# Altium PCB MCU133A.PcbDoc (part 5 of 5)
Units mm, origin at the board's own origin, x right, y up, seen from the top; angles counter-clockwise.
Board outline 58.42 x 139.7 mm, 4 copper layers (Top Signal, GND, PWR, Bottom Signal), stack 1.565 mm thick; 278 components, 226 nets, 1057 pads, 868 vias.
Unrouted connection lines stored in the file: 237.
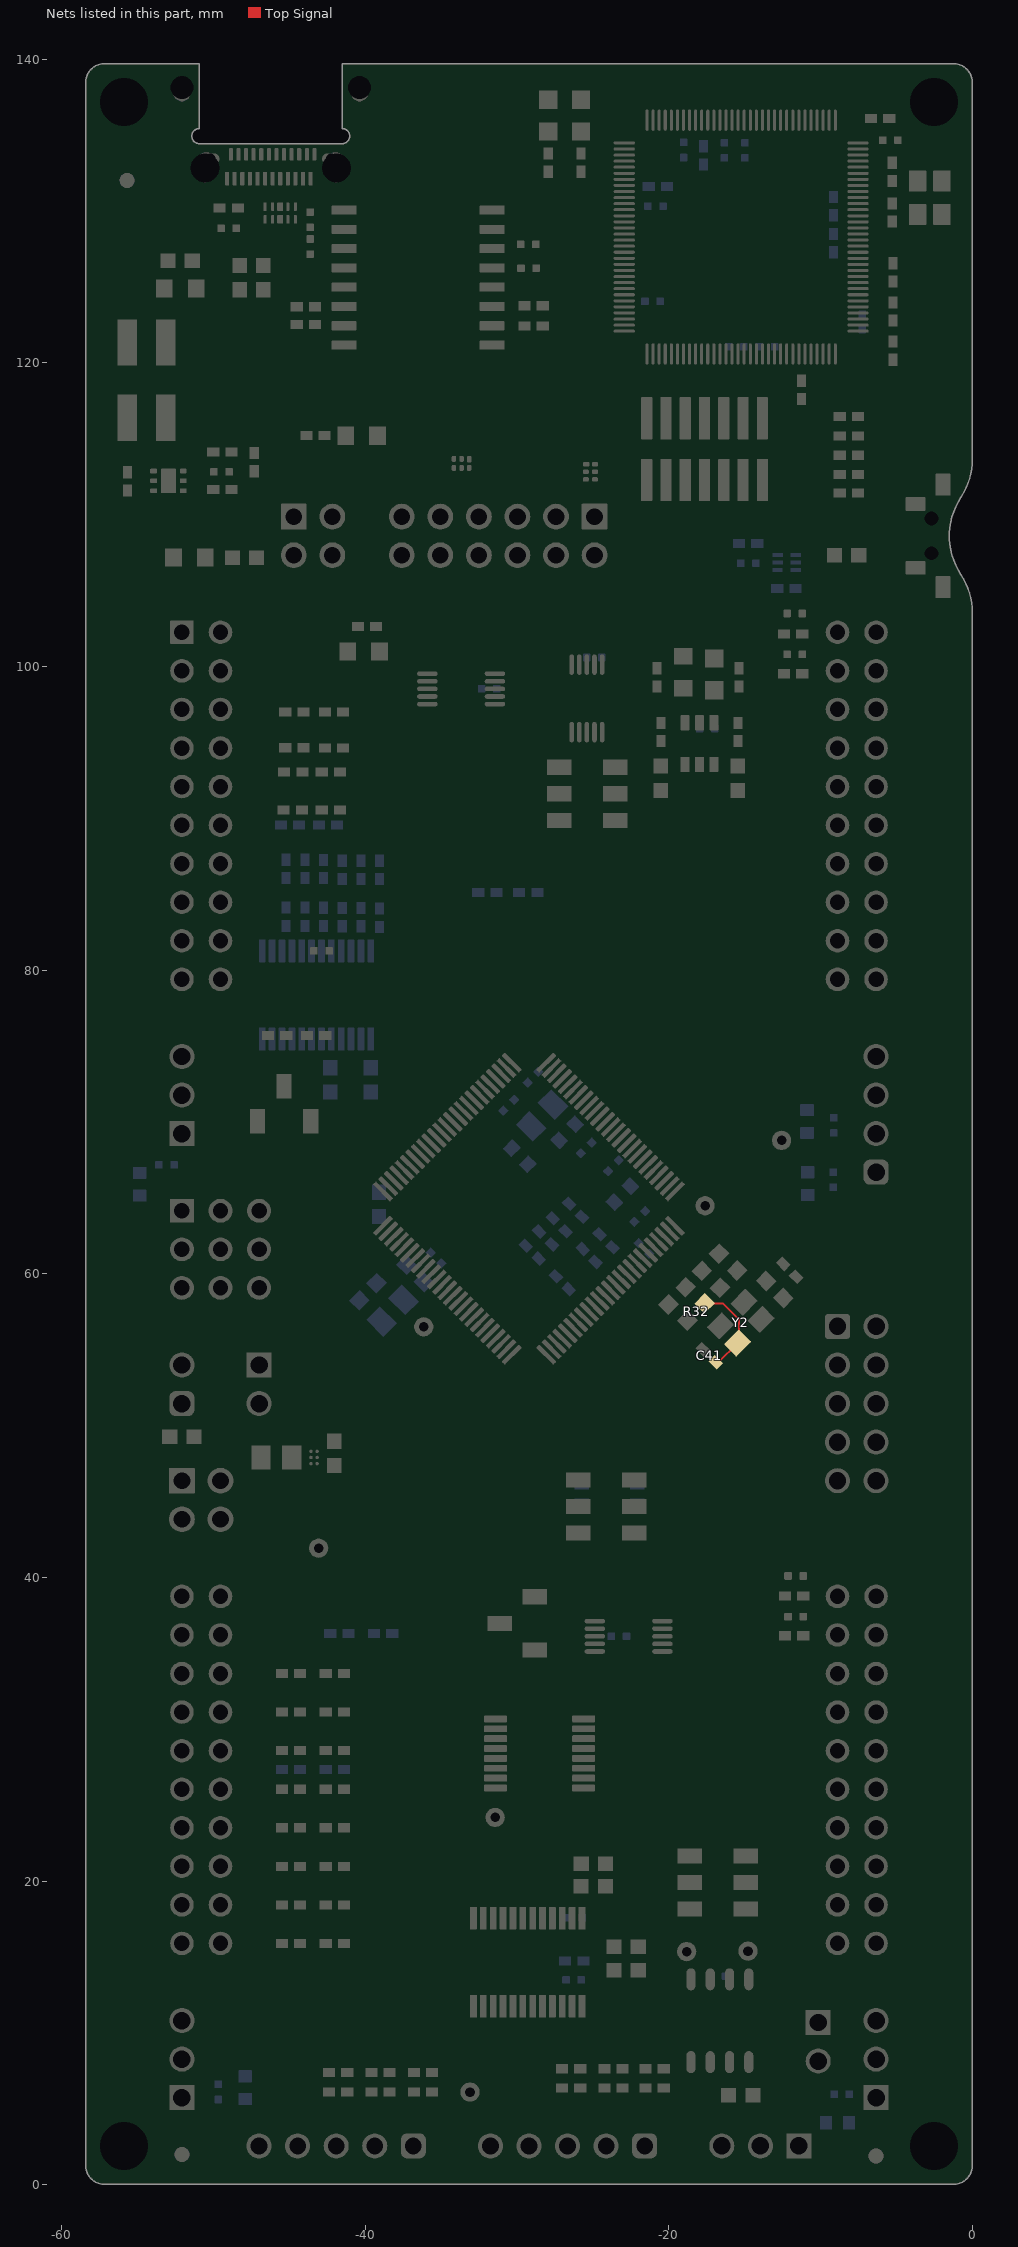
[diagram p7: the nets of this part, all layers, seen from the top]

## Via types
v1: diameter 0.45, hole 0.25, Top Signal to Bottom Signal, tented both sides, 822 vias
v2: diameter 0.5, hole 0.3, Top Signal to Bottom Signal, tented both sides, 22 vias
v3: diameter 0.7, hole 0.4, Top Signal to Bottom Signal, tented both sides, 17 vias
v4: diameter 0.4, hole 0.2, Top Signal to Bottom Signal, tented both sides, 5 vias
v5: diameter 0.5, hole 0.2, Top Signal to Bottom Signal, tented both sides, 2 vias

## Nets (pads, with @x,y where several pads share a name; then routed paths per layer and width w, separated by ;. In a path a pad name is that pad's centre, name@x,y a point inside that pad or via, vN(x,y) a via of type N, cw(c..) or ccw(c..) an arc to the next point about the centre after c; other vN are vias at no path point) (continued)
XTAL_X2: C41.1 R32.2 Y2.1 | length 6.3
  Top Signal w0.127: R32.2@-17.643,58.051 -16.445,58.051 -15.368,56.974 -15.368,55.54 Y2.1@-15.473,55.435 -16.737,54.171 C41.1@-16.909,54.171
pads on no net: FID1.1 FID2.1 FID3.1 FID4.1 FID5.1 FID6.1 J11.9 J102.7 M1.0 M2.0 M3.0 M4.0 M5.0 M6.0 M7.0 M8.0 M9.0 M10.0 M11.0 M12.0 M13.0 MH1.1 MH2.1 MH3.1 MH4.1 S1. U1.37 U2.1 U2.2 U2.5 U2.6 U2.11 U2.12 U2.13 U2.14 U2.15 U2.18 U2.19 U2.20 U2.21 U2.22 U2.23 U2.24 U2.25 U2.27 U2.29 U2.30 U2.31 U2.32 U2.41 U2.42 U2.43 U2.44 U2.45 U2.46 U2.49 U2.50 U2.53 U2.54 U2.56 U2.57 U2.65 U2.67 U2.71 U2.72 U2.73 U2.74 U2.75 U2.76 U2.77 U2.78 U2.81 U2.82 U2.83 U2.84 U2.85 U2.86 U2.91 U2.92 U2.95 U2.97 U2.98 U2.99 U2.100 U2.102 U2.103 U2.104 U2.105 U2.106 U2.107 U2.108 U2.109 U2.110 U2.111 U2.112 U2.116 U2.117 U2.118 U2.119 U2.120 U2.121 U2.123 U2.124 U2.125 U2.126 U2.127 U2.128 U5.2 U10.6 U15.5 U15.8 U16.3@-45.598,129.449 U16.8@-45.598,130.284 U17.3 U101.5 U101.7@-52.96,111.774 U101.7@-52.96,112.674 USB101.A2 USB101.A3 USB101.A8 USB101.A10 USB101.A11 USB101.B2 USB101.B3 USB101.B8 USB101.B10 USB101.B11

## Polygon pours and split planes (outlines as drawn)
+3V3_MCU on PWR "PWR-+3V3_MCU" (solid, remove dead copper, pour order 69): -53.35,102.942 -53.35,17.246 -51.084,14.98 -20.186,14.718 -19.096,13.738 -19.096,0.661 -0.636,0.649 -0.636,14.836 -0.636,108.214 -43.329,108.214 -43.329,104.613 -44.901,103.145 -53.215,103.145
+5V0_MCU on PWR "PWR_+5V0_MCU_P067" (solid, remove dead copper, pour order 67): -43.85,108.214 -57.774,108.214 -57.774,0.407 -57.786,0.395 -19.748,0.395 -19.748,13.507 -20.479,14.238 -51.355,14.238 -53.976,16.858 -53.976,102.661 -52.613,104.024 -44.747,104.024 -43.85,104.921
VDDIO on PWR "VDDIO" (solid, remove dead copper, pour order 65): -20.215,65.542 -18.79,64.117 -18.79,63.216 -20.969,61.037 -22.31,61.037 -23.207,61.935 -23.208,62.512 -23.226,62.529 -21.763,63.992 -21.763,65.194 -21.413,65.544
VDDIO on PWR "VDDIO" (solid, remove dead copper, pour order 63): -29.186,71.476 -29.185,72.202 -28.5,72.887 -27.56,72.887 -20.215,65.542 -20.215,64.777 -21.046,63.946 -21.656,63.946 -22.52,64.809
VDD on PWR "VDD" (solid, remove dead copper, pour order 61): -31.075,70.6 -23.326,62.851 -23.161,62.851 -22.099,63.912 -29.931,71.744
USB_GND on PWR "Top Signal-USB_GND" (solid, remove dead copper, pour order 49): -58.546,119.983 -38.524,119.983 -38.176,120.331 -38.176,139.771 -57.489,139.771 -57.489,139.697 -58.546,138.64
+5V0_XDS110 on PWR "PWR_+5V0_XDS110_P042" (solid, remove dead copper, pour order 42): -57.774,117.362 -57.774,108.979 -43.511,108.979 -43.511,117.362
+3V3_XDS110 on PWR "PWR-+3V3_XDS110" (solid, remove dead copper, pour order 12): -35.671,139.067 -0.636,139.067 -0.636,108.979 -43.316,108.979 -43.316,117.362 -37.25,117.362 -35.676,118.936
GND on Top Signal "GND-GND" (solid, remove dead copper, pour order 71): -58.443,117.316 -37.296,117.316 -35.611,119.001 -35.611,139.756 -1.013,139.756 0.014,138.729 0.014,0.864 -0.849,0.001 -57.499,0.001 -58.428,0.93 -58.428,117.276 -58.406,117.298
USB_GND on Top Signal "Top Signal-USB_GND" (solid, remove dead copper, pour order 20): -58.546,119.983 -38.524,119.983 -38.176,120.331 -38.176,139.771 -57.489,139.771 -57.489,139.697 -58.546,138.64
USB_GND on GND "Top Signal-USB_GND" (solid, remove dead copper, pour order 47): -58.546,119.983 -38.524,119.983 -38.176,120.331 -38.176,139.771 -57.489,139.771 -57.489,139.697 -58.546,138.64
GND on GND "GND-GND" (solid, remove dead copper, pour order 73): -58.443,117.316 -37.296,117.316 -35.611,119.001 -35.611,139.756 -1.013,139.756 0.014,138.729 0.014,0.864 -0.849,0.001 -57.499,0.001 -58.428,0.93 -58.428,117.276 -58.406,117.298
GND on Bottom Signal "GND-GND" (solid, remove dead copper, pour order 75): -58.443,117.314 -37.296,117.314 -35.611,118.999 -35.611,139.753 -1.013,139.754 0.014,138.727 0.014,0.862 -0.849,-0.001 -57.499,-0.001 -58.428,0.928 -58.428,117.274 -58.406,117.296
USB_GND on Bottom Signal "Top Signal-USB_GND" (solid, remove dead copper, pour order 51): -58.546,119.983 -38.524,119.983 -38.176,120.331 -38.176,139.771 -57.489,139.771 -57.489,139.697 -58.546,138.64

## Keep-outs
Keep-Out Layer:
  lines w0.2: -50.921,139.714 -57.151,139.714 ccw(c-57.151,138.444) -58.421,138.444 -58.421,1.284 ccw(c-57.151,1.284) -57.151,0.014 -1.271,0.014 ccw(c-1.271,1.284) -0.001,1.284 -0.001,103.519 ccw(c-4.615,103.519) -0.763,106.059 cw(c3.089,108.599) -0.763,111.139 ccw(c-4.615,113.679) -0.001,113.679 -0.001,138.444 ccw(c-1.271,138.444) -1.271,139.714 -41.521,139.714
  text ".Layer_Name" at -43.385,-21.695 h1.52

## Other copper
Top Signal:
  pour cut-out: -22.936,134.484 -22.936,122.084 -21.436,120.584 -9.036,120.584 -7.536,122.084 -7.536,134.484 -9.036,135.984 -21.436,135.984
  pour cut-out: -11.606,43.437 -11.328,43.714 -11.328,44.504 -12.488,44.504 -12.561,44.432 -12.051,43.922 -12.051,43.247
  pour cut-out: -27.074,45.616 -25.029,45.616 -24.879,45.466 -27.074,45.466
  pour cut-out: -16.032,20.853 -16.032,17.353 -13.371,17.353 -13.26,17.464 -13.507,17.711 -13.507,21.096 -15.789,21.096
  pour cut-out: -19.732,16.257 -19.494,16.019 -18.013,16.019 -17.532,16.5 -17.532,20.853 -19.651,20.853 -19.738,20.766 -19.732,20.76
  region net GND: -43.046,49.468 -43.283,49.231 -43.283,48.299 -43.181,48.198 -40.92,48.198 -40.616,48.503 -40.616,49.468
  pour cut-out: -28.324,90.815 -28.324,88.82 -22.424,88.82 -22.424,90.815
  region net +5V0_MCU: -43.257,48.02 -43.257,47.439 -42.696,46.877 -42.246,46.877 -41.682,47.441 -41.682,47.766 -41.784,47.868 -42.749,47.868 -42.902,48.02
  region net NetJ16_2: -43.571,47.498 -43.943,47.126 -43.943,46.217 -43.435,46.217 -43.232,46.42 -43.232,47.159
  region net NetL4_2: -43.571,47.898 -44.201,48.528 -44.4,48.528 -44.4,47.258 -44.211,47.258
  pour cut-out: -32.772,127.293 -32.772,121.818 -31.701,121.818 -31.701,122.038 -31.701,127.293 -32.752,127.293
  pour cut-out: -51.866,123.994 -52.316,123.994 -52.316,124.144 -51.866,124.144
  pour cut-out: -17.745,101.151 -18.311,101.155 -18.311,101.433 -17.752,101.433
  text ".Layer_Name" at -43.889,-21.576 h1.52
GND:
  text ".Layer_Name" at -42.044,-21.653 h1.52
PWR:
  text ".Layer_Name" at -41.965,-21.538 h1.52
Bottom Signal:
  pour cut-out: -18.018,56.269 -17.533,55.784 -17.533,55.209 -17.129,55.209 -16.574,55.764 -16.758,55.948 -16.758,56.434 -17.696,56.434 -17.783,56.347
  pour cut-out: -27.487,64.679 -27.585,64.58 -27.585,64.179 -26.361,62.955 -25.909,63.408 -25.909,63.463 -27.125,64.679
  pour cut-out: -37.472,56.728 -37.358,56.843 -37.358,57.037 -37.815,57.494 -37.999,57.494 -38.203,57.291 -38.203,57.239 -37.692,56.728
  region net GND: -23.3,66.63 -22.505,67.426 -21.718,67.426 -21.718,66.907 -21.591,66.78 -21.591,66.349 -22.089,65.851 -23.034,65.851 -23.3,66.117
  region net VDDIO: -28.414,71.028 -29.008,71.622 -29.008,71.921 -28.676,72.253 -27.916,71.492 -27.916,71.121 -28.03,71.007
  text ".Layer_Name" at -43.595,-21.642 h1.52

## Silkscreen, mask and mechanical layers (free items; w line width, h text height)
Top Overlay:
  drawing of 13411 lines, arcs and shapes, not listed
  text "XDS110 Out" at -20.951,118.378 h1.3
  text "+5V0" at -57.786,117.108 h1.3 r270
  text "GND" at -52.057,117.083 h1.3 r270
  text "XRSn" at -4.761,113.163 h1.85
  text "+5V0" at -44.921,105.984 h1.14 r270
  text "+3V3" at -42.381,105.984 h1.3 r270
  text "TDO" at -35.426,105.717 h1.3 r270
  text "TDI" at -37.966,105.678 h1.3 r270
  text "TCK" at -32.967,105.678 h1.3 r270
  text "TMS" at -30.396,105.678 h1.3 r270
  text "TXD<<" at -27.792,105.663 h1.3 r270
  text "RXD>>" at -25.218,105.611 h1.3 r270
  text "IO.0" at -13.586,105.611 h1.3
  text "IO.1" at -13.586,104.657 h1.3
  text "B11/D16" at -57.499,99.372 h1.3
  text "IO.57" at -4.713,99.339 h1.3
  text "A6" at -48.05,97.169 h1.3
  text "IO.32" at -4.713,96.915 h1.3
  text "IO.28" at -56.221,96.788 h1.3
  text "IO.2" at -12.352,96.788 h1.3
  text "D14" at -48.05,96.286 h1.3
  text "B2" at -48.102,94.629 h1.3
  text "1" at -22.772,94.426 h1.3
  text "1" at -28.863,94.315 h1.3
  text "IO.3" at -12.338,94.248 h1.3
  text "IO.31" at -4.713,94.248 h1.3
  text "C6" at -48.134,93.613 h1.3
  text "IO.29" at -56.215,92.978 h1.3
  text "A11" at -48.134,92.108 h1.3
  text "IO.10" at -12.942,91.708 h1.3
  text "XRSn" at -4.713,91.708 h1.3
  text "B10" at -48.058,91.206 h1.3
  text "SEL1" at -28.575,90.07 h1.3 r90
  text "SEL2" at -21.582,90.019 h1.3 r90
  text "A14" at -48.185,89.608 h1.3
  text "A7/B30" at -57.049,89.168 h1.3
  text "IO.11" at -12.899,89.168 h1.3
  text "IO.8" at -4.713,89.168 h1.3
  text "B14" at -48.083,88.706 h1.3
  text "0" at -29.008,88.104 h1.3
  text "0" at -22.706,88.025 h1.3
  text "A2" at -48.134,87.039 h1.3
  text "IO.9" at -55.628,86.656 h1.3
  text "IO.22" at -12.925,86.628 h1.3
  text "IO.17" at -4.713,86.628 h1.3
  text "B6" at -48.032,86.158 h1.3
  text "SEL1:" at -31.493,85.099 h1.3
  text "IO28," at -26.989,85.099 h1.3
  text "IO15," at -22.407,85.099 h1.3
  text "IO.24" at -56.232,84.088 h1.3
  text "IO.23" at -12.947,84.088 h1.3
  text "IO.21" at -4.713,84.088 h1.3
  text "B3" at -48.116,84.025 h1.3
  text "SEL2" at -31.493,83.829 h1.3
  text "IO29" at -26.989,83.829 h1.3
  text "IO56" at -22.407,83.829 h1.3
  text ":" at -29.757,82.293 h1.3
  text "0" at -30.646,82.191 h1.3
  text "0" at -29.284,82.191 h1.3
  text "XDS" at -26.37,82.191 h1.3
  text "BP" at -21.46,82.191 h1.3
  text "C1" at -48.134,81.929 h1.3
  text "IO.51" at -56.173,81.548 h1.3
  text "IO.4" at -12.958,81.548 h1.3
  text "IO.47" at -4.713,81.548 h1.3
  text "E11" at -48.109,81.04 h1.3
  text ":" at -29.735,80.705 h1.3
  text "0" at -30.624,80.604 h1.3
  text "1" at -29.1,80.604 h1.3
  text "XDS" at -26.37,80.604 h1.3
  text "NC" at -21.46,80.604 h1.3
  text "A1" at -48.134,79.262 h1.3
  text ":" at -29.73,79.13 h1.3
  text "1" at -30.492,79.029 h1.3
  text "0" at -29.257,79.029 h1.3
  text "BP" at -25.811,79.029 h1.3
  text "BP" at -21.46,79.029 h1.3
  text "IO.34" at -56.232,79.008 h1.3
  text "IO.5" at -12.942,79.008 h1.3
  text "IO.48" at -4.713,79.008 h1.3
  text "B7" at -48.032,78.373 h1.3
  text ":" at -29.721,77.57 h1.3
  text "1" at -30.483,77.469 h1.3
  text "1" at -29.086,77.469 h1.3
  text "BP" at -25.811,77.469 h1.3
  text "XDS" at -21.88,77.469 h1.3
  text "PGA Select" at -48.356,73.475 h1.3
  text "0" at -42.231,72.627 h1.3
  text "1" at -48.896,72.572 h1.3
  text "VDD" at -15.571,69.539 h1.3
  text "BP" at -49.015,67.896 h1.3
  text "J10" at -43.359,67.896 h1.3
  text "1" at -51.756,65.554 h1.6
  text "2" at -49.818,65.544 h1.6
  text "3" at -47.261,65.544 h1.6
  text "VDDIO" at -16.433,64.507 h1.3
  text "PGA_P" at -58.603,63.379 h1.6
  text "*" at -17.621,62.611 h0.64
  text "PGA_N" at -58.116,60.568 h1.6
  text "*" at -21.771,59.007 h0.64
  text "FSI" at -9.338,57.858 h1.3
  text "TXCLK" at -4.827,55.894 h1.3
  text "RXCLK" at -14.753,54.669 h1.3
  text "VDDA" at -37.517,54.249 h1.3
  text "VREFHI" at -44.489,53.663 h1.3
  text "ENABLE" at -57.581,53.269 h1.3
  text "+5V0" at -56.301,52.3 h1.3
  text "BOOST" at -57.122,51.276 h1.3
  text "TXD0" at -4.827,50.814 h1.3
  text "RXD0" at -13.844,50.56 h1.3
  text "LAUNCHXL- / F28P55X" at -35.154,49.037 h1.27 r0.23
  text "RXD1" at -13.336,48.147 h1.3
  text "TXD1" at -4.827,48.147 h1.3
  text "1" at -21.587,47.436 h1.3
  text "1" at -27.25,47.256 h1.3
  text "GND" at -5.368,43.273 h1.3
  text "+5V0 / TO / J7" at -47.523,43.009 h1.3
  text "+3V3 / TO / J5" at -57.341,43.001 h1.3
  text "GPIO24" at -27.701,42.473 h1.3 r90
  text "GPIO32" at -19.862,42.473 h1.3 r90
  text "IO.12" at -14.039,41.966 h1.3
  text "GND" at -42.114,41.645 h1.3
  text "IO.13" at -14.001,41.04 h1.3
  text "0" at -27.267,40.828 h1.3
  text "BOOT" at -25.524,40.729 h1.3
  text "0" at -21.714,40.729 h1.3
  text "BP" at -27.538,38.47 h1.3
  text "Q3" at -33.784,36.603 h1.3
  text "IO.27" at -4.84,35.828 h1.3
  text "C14" at -55.487,35.809 h1.3
  text "J13" at -27.703,34.482 h1.3
  text "B0" at -48.118,33.669 h1.3
  text "IO.15" at -56.234,33.288 h1.3
  text "IO.25" at -4.84,33.288 h1.3
  text "IO.6" at -12.336,33.161 h1.3
  text "C11" at -48.095,32.791 h1.3
  text "QEP Select" at -33.132,32.46 h1.3
  text "A10" at -48.133,31.179 h1.3
  text "IO.30" at -4.84,30.748 h1.3
  text "IO.7" at -12.333,30.494 h1.3
  text "B1" at -48.032,30.265 h1.3
  text "IO.56" at -56.255,29.478 h1.3
  text "A5" at -48.057,28.208 h1.3
  text "IO.37" at -12.924,28.208 h1.3
  text "XRSn" at -4.84,28.208 h1.3
  text "A4" at -48.108,26.114 h1.3
  text "A9" at -54.869,25.668 h1.3
  text "IO.35" at -12.903,25.668 h1.3
  text "IO.60" at -4.84,25.668 h1.3
  text "B8" at -48.057,25.236 h1.3
  text "CAN" at -17.866,24.242 h1.3
  text "+3V3" at -35.251,23.661 h1.3
  text "B4" at -48.057,23.485 h1.3
  text "ROUTE" at -18.374,23.248 h1.3
  text "IO.62" at -12.872,23.255 h1.3
  text "IO.14" at -56.251,23.128 h1.3
  text "IO.61" at -4.84,23.128 h1.3
  text "C8" at -48.133,22.585 h1.3
  text "BP" at -21.062,21.223 h1.3
  text "B5" at -48.057,20.863 h1.3
  text "IO.55" at -56.287,20.614 h1.3
  text "IO.20" at -4.84,20.588 h1.3
  text "IO.63" at -12.872,20.461 h1.3
  text "D15" at -48.088,19.982 h1.3
  text "A12" at -48.108,18.487 h1.3
  text "*" at -56.891,18.196 h0.64
  text "IO.18" at -56.251,18.048 h1.3
  text "IO.58" at -12.872,18.048 h1.3
  text "IO.26" at -4.84,18.048 h1.3
  text "XCVR" at -22.377,17.793 h1.3
  text "C5" at -48.057,17.565 h1.3
  text "A0" at -48.159,15.935 h1.3
  text "*" at -56.891,15.647 h0.64
  text "IO.19" at -56.245,15.508 h1.3
  text "IO.16" at -4.84,15.508 h1.3
  text "IO.33" at -12.915,15.381 h1.3
  text "B15" at -48.057,15.051 h1.3
  text "+5V0" at -31.991,5.804 h1.3
  text "CAN" at -13.717,4.332 h1.3
  text "EQEP3" at -43.547,4.255 h1.3
  text "EQEP1" at -28.361,4.255 h1.3
  text "GND" at -48.007,0.268 h1.3
  text "5V" at -45.086,0.268 h1.3
  text "3I" at -42.454,0.268 h1.3
  text "3B" at -40.006,0.268 h1.3
  text "3A" at -37.466,0.268 h1.3
  text "GND" at -32.767,0.268 h1.3
  text "5V" at -29.846,0.268 h1.3
  text "1I" at -27.071,0.268 h1.3
  text "1B" at -24.639,0.268 h1.3
  text "1A" at -22.099,0.268 h1.3
  text "GND" at -17.527,0.268 h1.3
  text "LO" at -14.606,0.268 h1.3
  text "HI" at -11.939,0.268 h1.3
  text ".Layer_Name" at -43.818,-21.621 h1.52
Bottom Overlay:
  drawing of 12861 lines, arcs and shapes, not listed
  text "LAUNCHXL-F28P55X / Development Kit" at -0.001,135.164 h2.54
  text "www.ti.com/launchpad" at -0.001,114.949 h2.54
  text "J3/J1" at -49.034,104.069 h1.7
  text "J2/J4" at -5.887,104.005 h1.7
  text "40" at -10.593,101.868 h1.3
  text "39" at -10.6,99.432 h1.3
  text "2" at -53.773,99.328 h1.3
  text "19" at -3.506,99.328 h1.3
  text "38" at -10.593,96.915 h1.3
  text "3" at -53.773,96.788 h1.3
  text "23" at -46.559,96.788 h1.3
  text "18" at -3.506,96.788 h1.3
  text "4" at -53.773,94.248 h1.3
  text "24" at -46.559,94.248 h1.3
  text "37" at -10.593,94.248 h1.3
  text "17" at -3.506,94.248 h1.3
  text "5" at -53.773,91.708 h1.3
  text "25" at -46.559,91.708 h1.3
  text "36" at -10.593,91.708 h1.3
  text "16" at -3.506,91.708 h1.3
  text "6" at -53.773,89.168 h1.3
  text "26" at -46.559,89.168 h1.3
  text "35" at -10.593,89.168 h1.3
  text "15" at -3.506,89.168 h1.3
  text "7" at -53.773,86.628 h1.3
  text "27" at -46.559,86.628 h1.3
  text "34" at -10.593,86.628 h1.3
  text "14" at -3.506,86.628 h1.3
  text "8" at -53.773,84.088 h1.3
  text "28" at -46.559,84.088 h1.3
  text "33" at -10.593,84.088 h1.3
  text "13" at -3.506,84.088 h1.3
  text "29" at -46.618,82.959 h1.3
  text "9" at -53.773,81.548 h1.3
  text "32" at -10.593,81.548 h1.3
  text "12" at -3.506,81.548 h1.3
  text "10" at -53.773,79.008 h1.3
  text "31" at -10.593,79.008 h1.3
  text "11" at -3.76,79.008 h1.3
  text "30" at -48.633,76.842 h1.3
  text "'.PRJ_Number'.PCB_Rev" at -23.94,48.274 h2.75
  text "J6/J8" at -5.784,40.626 h1.7
  text "J7/J5" at -49.011,40.603 h1.7
  text "80" at -10.593,38.495 h1.3
  text "42" at -53.773,35.828 h1.3
  text "79" at -10.593,35.828 h1.3
  text "59" at -3.379,35.817 h1.3
  text "43" at -53.773,33.288 h1.3
  text "63" at -46.559,33.288 h1.3
  text "78" at -10.593,33.288 h1.3
  text "58" at -3.379,33.277 h1.3
  text "44" at -53.773,30.748 h1.3
  text "64" at -46.559,30.748 h1.3
  text "77" at -10.593,30.748 h1.3
  text "57" at -3.379,30.737 h1.3
  text "45" at -53.773,28.208 h1.3
  text "65" at -46.559,28.208 h1.3
  text "76" at -10.593,28.208 h1.3
  text "56" at -3.379,28.197 h1.3
  text "46" at -53.773,25.668 h1.3
  text "66" at -46.559,25.668 h1.3
  text "75" at -10.593,25.668 h1.3
  text "55" at -3.379,25.657 h1.3
  text "47" at -53.773,23.128 h1.3
  text "67" at -46.559,23.128 h1.3
  text "74" at -10.593,23.128 h1.3
  text "54" at -3.379,23.117 h1.3
  text "48" at -53.773,20.588 h1.3
  text "68" at -46.559,20.588 h1.3
  text "73" at -10.593,20.588 h1.3
  text "53" at -3.379,20.577 h1.3
  text "49" at -53.773,18.048 h1.3
  text "69" at -46.559,18.048 h1.3
  text "72" at -10.593,18.048 h1.3
  text "52" at -3.379,18.037 h1.3
  text "TP8" at -18.137,16.229 h1.14
  text "TP7" at -13.778,16.229 h1.14
  text "50" at -53.773,15.508 h1.3
  text "70" at -46.559,15.508 h1.3
  text "71" at -10.593,15.508 h1.3
  text "51" at -3.633,15.508 h1.3
  text "CANRX" at -18.137,13.738 h1.14
  text "CANTX" at -12.804,13.738 h1.14
  text "For evaluation only; not FCC approved for resale." at -13.971,3.79 h1.52
  text "GND" at -45.975,0.395 h1.3
  text "5V" at -43.816,0.395 h1.3
  text "3I" at -41.276,0.395 h1.3
  text "3B" at -38.736,0.395 h1.3
  text "3A" at -36.196,0.395 h1.3
  text "GND" at -30.735,0.395 h1.3
  text "5V" at -28.576,0.395 h1.3
  text "1I" at -26.248,0.395 h1.3
  text "1B" at -23.623,0.395 h1.3
  text "1A" at -21.083,0.395 h1.3
  text ".Layer_Name" at -43.392,-21.623 h1.52
Top Paste:
  text ".Layer_Name" at -43.719,-21.896 h1.52
Bottom Paste:
  text ".Layer_Name" at -43.601,-21.778 h1.52
Top Solder:
  text ".Layer_Name" at -43.841,-21.919 h1.52
Bottom Solder:
  text ".Layer_Name" at -43.486,-21.766 h1.52
Drill Guide:
  text ".Layer_Name" at -43.587,-21.766 h1.52
M1 Board Outline:
  lines w0.254: -50.921,139.714 -57.151,139.714 ccw(c-57.151,138.444) -58.421,138.444 -58.421,1.284 ccw(c-57.151,1.284) -57.151,0.014 -1.271,0.014 ccw(c-1.271,1.284) -0.001,1.284 -0.001,103.519 ccw(c-4.615,103.519) -0.763,106.059 cw(c3.089,108.599) -0.763,111.139 ccw(c-4.615,113.679) -0.001,113.679 -0.001,138.444 ccw(c-1.271,138.444) -1.271,139.714 -41.521,139.714
  text ".Layer_Name" at -43.812,-21.787 h1.52
M2 Board Dimensions:
  text ".Layer_Name" at -43.661,-21.828 h1.52
M3 3D STEP Top:
  text ".Layer_Name" at -43.841,-21.69 h1.52
M4 3D STEP Bottom:
  text ".Layer_Name" at -43.811,-21.742 h1.52
M5 Assembly Top:
  lines w0.254: -65.825,-23.523 101.815,-23.523 ; -65.825,-18.359 101.866,-18.359 ; -65.825,-13.194 -65.825,-28.688 35.902,-28.688 101.866,-28.688 101.866,-13.194 -65.812,-13.194 -65.812,-28.688 -25.795,-28.688 ; -3.214,-28.688 -3.214,-13.194 ; 28.968,-18.359 28.968,-13.194 ; 50.304,-18.359 50.304,-13.194 ; 66.103,-28.853 66.103,-23.701
  text "COMPONENTS MARKED 'DNP' SHOULD NOT BE POPULATED." at -29.109,-7.987 h1.52
  text "ASSEMBLY VARIANT:" at -29.122,-10.921 h1.52
  text ".VariantName" at -2.808,-10.921 h1.52
  text "PCB VIEWED FROM TOP SIDE" at -64.212,-16.551 h1.52
  text "BOARD #:" at -1.309,-16.551 h1.52
  text ".PRJ_Number" at 12.547,-16.551 h1.52
  text "REV:" at 33.997,-16.551 h1.52
  text ".PCB_Rev" at 41.401,-16.551 h1.52
  text "SVN REV:" at 55.282,-16.551 h1.52
  text ".VersionControl_RevNumber" at 68.135,-16.551 h1.52
  text ".Layer_Name" at -43.676,-21.741 h1.52
  text "TID #:" at -1.309,-21.716 h1.52
  text ".TID" at 12.547,-21.716 h1.52
  text "PLOT NAME =" at -64.212,-26.931 h1.52
  text ".plot_File_Name" at -43.752,-26.931 h1.52
  text "GENERATED    :" at -1.258,-26.931 h1.52
  text ".Print_Date" at 20.827,-26.931 h1.52
  text ".Print_Time" at 39.344,-26.931 h1.52
  text "TEXAS INSTRUMENTS" at 71.462,-26.931 h1.52
M6 Assembly Bottom:
  lines w0.254: -65.812,-18.384 101.878,-18.384 ; -65.762,-23.549 101.878,-23.549 ; -30.049,-28.878 -30.049,-23.727 ; -14.25,-18.384 -14.25,-13.219 ; 7.086,-18.384 7.086,-13.219 ; 39.267,-28.713 39.267,-13.219 ; 61.848,-28.713 101.866,-28.713 101.866,-13.219 -65.812,-13.219 -65.812,-28.713 0.151,-28.713 101.878,-28.713 101.878,-13.219
  text "COMPONENTS MARKED 'DNP' SHOULD NOT BE POPULATED." at 96.608,-7.987 h1.52
  text ".VariantName" at 70.09,-10.933 h1.52
  text "ASSEMBLY VARIANT:" at 96.481,-10.933 h1.52
  text ".VersionControl_RevNumber" at -32.081,-16.576 h1.52
  text "SVN REV:" at -19.229,-16.576 h1.52
  text ".PCB_Rev" at -5.348,-16.576 h1.52
  text "REV:" at 2.056,-16.576 h1.52
  text ".PRJ_Number" at 23.507,-16.576 h1.52
  text "BOARD #:" at 37.362,-16.576 h1.52
  text "PCB VIEWED FROM BOTTOM SIDE" at 100.266,-16.576 h1.52
  text ".Layer_Name" at -43.651,-21.754 h1.52
  text ".TID" at 23.507,-21.741 h1.52
  text "TID #:" at 37.362,-21.741 h1.52
  text "TEXAS INSTRUMENTS" at -35.409,-26.957 h1.52
  text ".Print_Time" at -3.29,-26.957 h1.52
  text ".Print_Date" at 15.226,-26.957 h1.52
  text "GENERATED    :" at 37.312,-26.957 h1.52
  text ".plot_File_Name" at 79.806,-26.957 h1.52
  text "PLOT NAME =" at 100.266,-26.957 h1.52
M7 LPKF Text Top:
  text ".Layer_Name" at -43.651,-21.647 h1.52
M8 LPKF Text Bottom:
  text ".Layer_Name" at -43.635,-21.78 h1.52
M9 Title Sheet:
  drawing of 57 lines, arcs and shapes, not listed
  text "1" at -39.629,204.141 h1.78
  text "2" at 23.761,204.141 h1.78
  text "3" at 86.99,204.141 h1.78
  text "4" at 150.659,204.141 h1.78
  text "5" at 214.134,204.141 h1.78
  text "6" at 277.761,204.141 h1.78
  text "A" at -69,175.109 h1.78
  text "A" at 306.92,175.109 h1.78
  text "B" at -69,114.657 h1.78
  text "B" at 306.92,114.657 h1.78
  text "C" at -69,54.332 h1.78
  text "C" at 306.92,54.332 h1.78
  text "PROJECT TITLE:" at 229.704,7.063 h1.14
  text ".PRJ_Title" at 230.974,3.676 h1.78
  text "DESIGNED FOR:" at 229.704,-0.583 h1.14
  text ".PRJ_Customer" at 230.974,-4.139 h1.78
  text "D" at -69,-5.866 h1.78
  text "D" at 306.92,-5.866 h1.78
  text "FILE NAME:" at 229.704,-8.203 h1.14
  text ".PCB_File_Name_No_Path" at 230.974,-11.251 h1.78
  text "Texas Instruments (TI) and/or its licensors do not warrant the accuracy or completeness of this specification" at 103.479,-15.362 h1.14
  text "ENGINEER:" at 229.704,-15.569 h1.14
  text "LAYOUT BY:" at 267.931,-15.569 h1.14
  text "or any information contained therein. TI and/or its licensors do not warrant that this design will meet" at 102.336,-18.223 h1.14
  text ".PRJ_Engineer" at 230.974,-19.506 h1.78
  text ".PCB_Layout" at 269.214,-19.506 h1.78
  text "the specifications, will be suitable for your application or fit for any particular purpose, or will operate in" at 102.336,-21.085 h1.14
  text ".Layer_Name" at -43.765,-21.792 h1.52
  text "ALTIUM DESIGNER VERSION:" at 267.931,-23.443 h1.14
  text "an implementation. TI and/or its licensors do not warrant that the design is production worthy. You should" at 102.336,-23.947 h1.14
  text "completely validate and test your design implementation to confirm the system functionality for your application." at 103.479,-26.808 h1.14
  text ".print_Scale" at 230.974,-26.829 h1.78
  text ".Application_BuildNumber" at 269.214,-26.829 h1.78
  text "1" at -39.629,-32.079 h1.78
  text "2" at 23.761,-32.079 h1.78
  text "3" at 86.99,-32.079 h1.78
  text "4" at 150.659,-32.079 h1.78
  text "5" at 214.134,-32.079 h1.78
  text "6" at 277.761,-32.079 h1.78
M10 Fab Notes:
  drawing of 189 lines, arcs and shapes, not listed
  text "DESIGN INFORMATION" at 256.133,161.639 h1.52
  text "MIN. TRACK WIDTH:" at 239.761,158.283 h1.52
  text "5" at 267.606,158.283 h1.52
  text "MIL" at 271.537,158.283 h1.52
  text "0.15" at 265.048,155.335 h1.52
  text "MIN. CLEARANCE:" at 239.761,155.13 h1.52
  text "mm" at 271.537,155.13 h1.52
  text "MIN. VIA PAD SIZE:" at 239.761,151.977 h1.52
  text "0.45" at 265.048,151.977 h1.52
  text "mm" at 271.537,151.977 h1.52
  text "0.05mm (2MIL)" at 257.414,148.678 h1.52
  text "MINIMUM ANNULAR RING" at 231.399,148.469 h1.52
  text "EXTERNAL" at 275.397,148.469 h1.52
  text "PER" at 236.479,145.672 h1.52
  text "IPC-D-275 CLASS 2 LEVEL C" at 242.067,145.671 h1.52
  text "MIL, HOLES" at 279.868,143.119 h1.52
  text "+/-" at 269.899,142.901 h1.52
  text "+/-" at 291.591,142.901 h1.52
  text "REGISTRATION TOLERANCES:" at 231.399,142.874 h1.52
  text "METAL" at 261.873,142.874 h1.52
  text "5" at 276.509,142.874 h1.52
  text "3" at 297.667,142.874 h1.52
  text "MIL" at 300.62,142.874 h1.52
  text "HOLE SIZE TOLERANCE (UNLESS OTHERWISE SPECIFIED):" at 231.399,140.377 h1.52
  text "+/-" at 291.591,140.304 h1.52
  text "5" at 297.667,140.277 h1.52
  text "MIL" at 300.62,140.277 h1.52
  text "MATERIAL:" at 229.5,136.781 h1.52
  text "FR-4 High Tg" at 254.555,133.516 h1.52
  text "X" at 250.887,133.313 h1.52
  text "FR-408" at 240.193,133.199 h1.52
  text "OTHER" at 277.988,133.199 h1.52
  text "62 MIL (1.6mm) +/-10%" at 248.324,129.566 h1.52
  text "X" at 245.273,129.503 h1.52
  text "THICKNESS:" at 231.399,129.357 h1.52
  text "OTHER" at 280.96,129.357 h1.52
  text "TOLERANCE:" at 231.399,125.844 h1.52
  text "ANSI IPC-6012 TYPE 3 CLASS 2" at 257.465,125.844 h1.52
  text "IPC-A600" at 274.878,122.62 h1.85
  text "OTHER +/-" at 257.465,122.181 h1.52
  text "X" at 253.161,122.112 h1.52
  text "BOW & TWIST:" at 231.399,118.493 h1.52
  text "ANSI IPC-6012 TYPE 3 CLASS 2" at 257.465,118.493 h1.52
  text "X" at 252.907,115.381 h1.52
  text "IPC-A600" at 274.878,114.873 h1.85
  text "OTHER +/-" at 257.465,114.767 h1.52
  text "DRILLING:" at 229.5,111.45 h1.52
  text "NC_DRILL FILES" at 274.229,108.778 h1.52
  text "REFERENCE:" at 231.399,108.678 h1.52
  text "X" at 248.093,108.675 h1.52
  text "AS SHOWN" at 252.614,108.678 h1.52
  text "X" at 270.978,108.678 h1.52
  text "OTHER" at 281.798,105.065 h1.52
  text "PTH COPPER THICKNESS:" at 231.391,104.975 h1.52
  text "X" at 260.327,104.975 h1.52
  text "20-30 um" at 263.578,104.975 h1.52
  text "BOARD FINISH:" at 229.5,101.226 h1.52
  text "SILKSCREEN:" at 233.442,98.429 h1.52
  text "X" at 257.77,98.429 h1.52
  text "TOP" at 260.742,98.429 h1.52
  text "X" at 270.724,98.429 h1.52
  text "BOTTOM" at 273.721,98.429 h1.52
  text "SILKSCREEN COLOR:" at 233.442,94.487 h1.52
  text "X" at 257.745,94.487 h1.52
  text "WHITE" at 260.742,94.487 h1.52
  text "OTHER" at 273.721,94.487 h1.52
  text "RED" at 289.915,91.098 h2.03
  text "GREEN" at 264.069,90.843 h1.52
  text "OTHER" at 279.766,90.843 h1.52
  text "X" at 276.046,90.743 h1.52
  text "SOLDER RESIST COLOR:" at 233.442,90.669 h1.52
  text "MATTE" at 264.069,86.925 h1.52
  text "SEMI-GLOSS" at 279.755,86.909 h1.52
  text "IMMERSION GOLD (ENIG)" at 256.449,82.537 h1.52
  text "ENEPIG" at 290.423,82.354 h1.52
  text "SURFACE FINISH:" at 229.5,82.328 h1.52
  text "IMM. TIN/SILVER OR EQUIV" at 237.87,78.84 h1.52
  text "X" at 234.111,78.805 h1.52
  text "OTHER" at 274.229,78.74 h1.52
  text "ARRAY/PANEL:" at 229.5,74.794 h1.52
  text "CUT AND TRIM PER M1 BOARD OUTLINE" at 256.449,74.585 h1.52
  text "X" at 251.916,74.538 h1.52
  text "N.C. ROUTE" at 256.449,71.131 h1.52
  text "V. SCORE" at 278.445,71.131 h1.52
  text "CERTIFICATION:" at 229.5,67.852 h1.52
  text "MATERIALS AND WORKMANSHIP FOR ALL PCBS" at 247.915,67.852 h1.52
  text "TO MEET OR EXCEED THE REQUIREMENTS OF:" at 247.915,65.462 h1.52
  text "X" at 283.843,62.254 h1.52
  text "X" at 238.707,62.195 h1.52
  text "ANSI IPC-A-600F CLASS ->" at 241.958,62.195 h1.52
  text "2" at 286.612,62.195 h1.52
  text "1" at 278.611,62.157 h1.52
  text "3" at 295.603,62.157 h1.52
  text "X" at 259.332,58.444 h1.52
  text "RoHS" at 262.583,58.444 h1.52
  text "OTHER" at 278.951,58.444 h1.52
  text "PER ORDER" at 289.036,58.444 h1.52
  text "ALL BOARDS MUST MEET OR EXCEED UL94-V0 REQUIREMENTS." at 230.199,54.537 h1.52
  text "PCB MUST BEAR THE UL94V-0 UL REGISTERED MATERIAL ID NUMBER" at 230.199,51.589 h1.52
  text "ADDITIONAL REQUIREMENTS:" at 229.5,47.285 h1.52
  text "MICROSECTION:" at 231.399,44.564 h1.52
  text "YES" at 254.404,44.564 h1.52
  text "X" at 261.467,40.959 h1.52
  text "REQUIRED" at 276.286,40.898 h1.52
  text "BARE BOARD ELEC. TEST:" at 231.399,40.826 h1.52
  text "NONE" at 264.564,40.826 h1.52
  text "PER ORDER" at 291.323,40.826 h1.52
  text "XX MIL VIAS REQUIRE NON-CONDUCTIVE FILL AND PLANARIZE" at 235.67,35.62 h1.5
  text "XX MIL VIAS REQUIRE CONDUCTIVE FILL AND PLANARIZE" at 235.873,32.979 h1.52
  text "OUTER XX MIL VIAS REQUIRE 50 OHM SINGLE-ENDED IMPEDANCE" at 235.848,28.829 h1.47
  text "LAYER 2 & 3 (INNER LAYERS) XX MIL WIDE, XX MIL SPACE / TRACES REQUIRE 100 OHM DIFFERENTIAL IMPEDANCE" at 235.645,22.842 h1.52
  text ".Layer_Name" at -43.489,-21.763 h1.52
M12 Stackup:
  drawing of 295 lines, arcs and shapes, not listed
  text "Use Standard 4 Layer Stackup" at 119.538,152.553 h6.35
  text "Layer" at 106.418,145.988 h1.52
  text "Name" at 116.83,145.988 h1.52
  text "Material" at 140.446,145.988 h1.52
  text "Thickness" at 162.284,145.988 h1.52
  text "Constant" at 178.79,145.988 h1.52
  text "Board Layer Stack" at 193.264,145.988 h1.52
  text "Top Overlay" at 116.83,142.94 h1.52
  text "Top Solder" at 116.83,139.892 h1.52
  text "Solder Resist" at 140.446,139.892 h1.52
  text "0.40mil" at 162.284,139.892 h1.52
  text "3.5" at 178.79,139.892 h1.52
  text "1" at 106.418,136.844 h1.52
  text "Top Signal" at 116.83,136.844 h1.52
  text "1.40mil" at 162.284,136.844 h1.52
  text "Dielectric 1" at 116.83,133.796 h1.52
  text "FR-4" at 140.446,133.796 h1.52
  text "8.00mil" at 162.284,133.796 h1.52
  text "4.2" at 178.79,133.796 h1.52
  text "2" at 106.418,130.748 h1.52
  text "GND" at 116.83,130.748 h1.52
  text "1.40mil" at 162.284,130.748 h1.52
  text "Dielectric 2" at 116.83,127.7 h1.52
  text "FR-4" at 140.446,127.7 h1.52
  text "40.00mil" at 162.284,127.7 h1.52
  text "4.2" at 178.79,127.7 h1.52
  text "3" at 106.418,124.652 h1.52
  text "PWR" at 116.83,124.652 h1.52
  text "1.40mil" at 162.284,124.652 h1.52
  text "Dielectric 3" at 116.83,121.604 h1.52
  text "FR-4" at 140.446,121.604 h1.52
  text "8.00mil" at 162.284,121.604 h1.52
  text "4.2" at 178.79,121.604 h1.52
  text "4" at 106.418,118.556 h1.52
  text "Bottom Signal" at 116.83,118.556 h1.52
  text "1.40mil" at 162.284,118.556 h1.52
  text "Bottom Solder" at 116.83,115.508 h1.52
  text "Solder Resist" at 140.446,115.508 h1.52
  text "0.40mil" at 162.284,115.508 h1.52
  text "3.5" at 178.79,115.508 h1.52
  text "Bottom Overlay" at 116.83,112.46 h1.52
  text ".Layer_Name" at -43.841,-21.843 h1.52
M13 Component Bodies Top:
  text ".Layer_Name" at -43.614,-21.721 h1.52
M14 Component Bodies Bottom:
  text ".Layer_Name" at -43.806,-21.57 h1.52
M15 Courtyards Top:
  text ".Layer_Name" at -43.583,-21.594 h1.52
M16 Courtyards Bottom:
  text ".Layer_Name" at -43.675,-21.626 h1.52
Drill Drawing:
  drawing of 184 lines, arcs and shapes, not listed
  text "Symbol" at 134.198,100.158 h1.83
  text "Quantity" at 141.832,100.158 h1.83
  text "Finished Hole Size" at 150.265,100.158 h1.83
  text "Plated" at 166.434,100.158 h1.83
  text "Hole Type" at 173.016,100.158 h1.83
  text "Drill Layer Pair" at 182.545,100.158 h1.83
  text "Hole Tolerance" at 201.739,100.158 h1.83
  text "2" at 141.832,97 h1.52
  text "35.43mil (0.900mm)" at 150.265,97 h1.52
  text "NPTH" at 166.434,97 h1.52
  text "Round" at 173.016,97 h1.52
  text "Top Signal - Bottom Signal" at 182.545,97 h1.52
  text "4" at 141.832,93.842 h1.52
  text "125.00mil (3.175mm)" at 150.265,93.842 h1.52
  text "NPTH" at 166.434,93.842 h1.52
  text "Round" at 173.016,93.842 h1.52
  text "Top Signal - Bottom Signal" at 182.545,93.842 h1.52
  text "7" at 141.832,90.685 h1.52
  text "7.87mil (0.200mm)" at 150.265,90.685 h1.52
  text "PTH" at 166.434,90.685 h1.52
  text "Round" at 173.016,90.685 h1.52
  text "Top Signal - Bottom Signal" at 182.545,90.685 h1.52
  text "497" at 141.832,87.527 h1.52
  text "9.84mil (0.250mm)" at 150.265,87.527 h1.52
  text "PTH" at 166.434,87.527 h1.52
  text "Round" at 173.016,87.527 h1.52
  text "Top Signal - Bottom Signal" at 182.545,87.527 h1.52
  text "325" at 141.832,84.369 h1.52
  text "9.84mil (0.250mm)" at 150.265,84.369 h1.52
  text "PTH" at 166.434,84.369 h1.52
  text "Round" at 173.016,84.369 h1.52
  text "Top Signal - Bottom Signal" at 182.545,84.369 h1.52
  text "+0.00mil" at 201.739,84.369 h1.52
  text "1" at 141.832,81.212 h1.52
  text "11.81mil (0.300mm)" at 150.265,81.212 h1.52
  text "PTH" at 166.434,81.212 h1.52
  text "Round" at 173.016,81.212 h1.52
  text "Top Signal - Bottom Signal" at 182.545,81.212 h1.52
  text "A" at 133.556,80.958 h1.4
  text "21" at 141.832,78.054 h1.52
  text "11.81mil (0.300mm)" at 150.265,78.054 h1.52
  text "PTH" at 166.434,78.054 h1.52
  text "Round" at 173.016,78.054 h1.52
  text "Top Signal - Bottom Signal" at 182.545,78.054 h1.52
  text "+0.00mil" at 201.739,78.054 h1.52
  text "16" at 141.832,74.896 h1.52
  text "15.75mil (0.400mm)" at 150.265,74.896 h1.52
  text "PTH" at 166.434,74.896 h1.52
  text "Round" at 173.016,74.896 h1.52
  text "Top Signal - Bottom Signal" at 182.545,74.896 h1.52
  text "1" at 141.832,71.738 h1.52
  text "15.75mil (0.400mm)" at 150.265,71.738 h1.52
  text "PTH" at 166.434,71.738 h1.52
  text "Round" at 173.016,71.738 h1.52
  text "Top Signal - Bottom Signal" at 182.545,71.738 h1.52
  text "+0.00mil" at 201.739,71.738 h1.52
  text "B" at 133.556,71.485 h1.4
  text "8" at 141.832,68.581 h1.52
  text "25.00mil (0.635mm)" at 150.265,68.581 h1.52
  text "PTH" at 166.434,68.581 h1.52
  text "Round" at 173.016,68.581 h1.52
  text "Top Signal - Bottom Signal" at 182.545,68.581 h1.52
  text "89" at 141.832,65.423 h1.52
  text "40.16mil (1.020mm)" at 150.265,65.423 h1.52
  text "PTH" at 166.434,65.423 h1.52
  text "Round" at 173.016,65.423 h1.52
  text "Top Signal - Bottom Signal" at 182.545,65.423 h1.52
  text "10" at 141.832,62.265 h1.52
  text "43.31mil (1.100mm)" at 150.265,62.265 h1.52
  text "PTH" at 166.434,62.265 h1.52
  text "Round" at 173.016,62.265 h1.52
  text "Top Signal - Bottom Signal" at 182.545,62.265 h1.52
  text "+/-1.97mil" at 201.739,62.265 h1.52
  text "20" at 141.832,59.107 h1.52
  text "43.31mil (1.100mm)" at 150.265,59.107 h1.52
  text "PTH" at 166.434,59.107 h1.52
  text "Round" at 173.016,59.107 h1.52
  text "Top Signal - Bottom Signal" at 182.545,59.107 h1.52
  text "32" at 141.832,55.95 h1.52
  text "45.28mil (1.150mm)" at 150.265,55.95 h1.52
  text "PTH" at 166.434,55.95 h1.52
  text "Round" at 173.016,55.95 h1.52
  text "Top Signal - Bottom Signal" at 182.545,55.95 h1.52
  text "2" at 141.832,52.792 h1.52
  text "27.56mil (0.700mm)" at 150.265,52.792 h1.52
  text "PTH" at 166.434,52.792 h1.52
  text "Slot" at 173.016,52.792 h1.52
  text "Top Signal - Bottom Signal" at 182.545,52.792 h1.52
  text "2" at 141.832,49.634 h1.52
  text "59.06mil (1.500mm)" at 150.265,49.634 h1.52
  text "PTH" at 166.434,49.634 h1.52
  text "Slot" at 173.016,49.634 h1.52
  text "Top Signal - Bottom Signal" at 182.545,49.634 h1.52
  text "2" at 141.832,46.476 h1.52
  text "74.80mil (1.900mm)" at 150.265,46.476 h1.52
  text "PTH" at 166.434,46.476 h1.52
  text "Slot" at 173.016,46.476 h1.52
  text "Top Signal - Bottom Signal" at 182.545,46.476 h1.52
  text "1039 Total" at 141.832,43.319 h1.52
  text "Slot definitions :" at 134.198,41.108 h1.52
  text "Routed Path Length" at 145.646,41.108 h1.52
  text "= Calculated from tool start centre position to tool end centre position." at 159.355,41.108 h1.52
  text "Hole Length" at 145.646,39.845 h1.52
  text "= Routed Path Length + Tool Size = Slot length as defined in the PCB layout" at 154.281,39.845 h1.52
  text ".Layer_Name" at -43.354,-21.647 h1.52
Mechanical 17:
  text ".Layer_Name" at -43.536,-21.748 h1.52
Mechanical 18:
  text ".Layer_Name" at -43.486,-21.817 h1.52
Mechanical 19:
  text ".Layer_Name" at -43.482,-21.626 h1.52

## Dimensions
-58.421,0.014 to -58.421,139.714 on M2 Board Dimensions
-58.421,0.014 to -0.001,0.014 on M2 Board Dimensions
